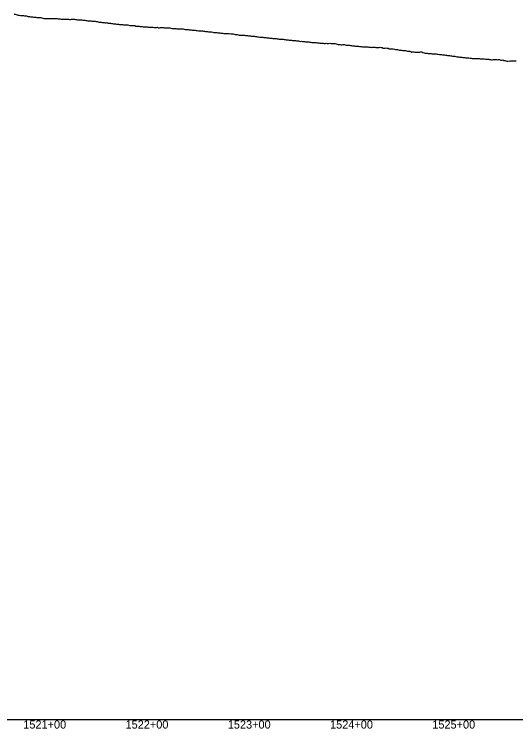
# Model space of a CAD drawing. Extents: x -3793 to 50787, y -1075 to 6138.
# Drawn here: x 39450 to 39940, y 991 to 1689 of the extents above; entities that cross this region are included whole.
import ezdxf

# ---------------------------------------------------------------- set-up
doc = ezdxf.new("R2010")
doc.units = 0
for name, color, linetype in [('RD_DDB_Profile_EX', 7, 'Continuous'), ('RD_DDB_StaTX', 7, 'Continuous'), ('RD_GPK_Profile_Cell', 7, 'Continuous')]:
    doc.layers.add(name, color=color, linetype=linetype)

msp = doc.modelspace()

# ---------------------------------------------------------------- linework, layer by layer
at = {"layer": 'RD_DDB_Profile_EX'}
for points in [[(39449.537684, 1689.40736), (39450.542169, 1689.40942), (39451.544989, 1689.208105), (39452.53964, 1688.9621), (39453.542457, 1688.56125), (39454.545276, 1688.459445), (39455.539896, 1688.36386), (39456.542717, 1688.311505), (39457.54554, 1688.259075), (39458.538528, 1688.15812), (39459.541346, 1688.00625), (39460.54417, 1687.85403), (39461.537143, 1687.752555), (39462.791116, 1687.374955), (39463.543266, 1687.301515), (39464.536597, 1687.102635), (39465.540058, 1687.00463), (39466.54352, 1686.956515), (39467.536879, 1686.807795), (39468.540329, 1686.71492), (39469.543797, 1686.51695), (39470.547266, 1686.46765), (39471.540601, 1686.367695), (39472.544069, 1686.317545), (39473.547537, 1686.120875), (39474.540963, 1686.21834), (39475.544439, 1686.170315), (39476.547915, 1685.825485), (39477.541364, 1685.629255), (39478.54473, 1685.185275), (39479.548205, 1685.13814), (39480.541674, 1685.190135), (39481.545157, 1685.33708), (39482.54864, 1685.43415), (39483.552123, 1685.334445), (39484.545467, 1685.236235)], [(39484.545467, 1685.236235), (39485.54895, 1685.238005), (39486.552434, 1685.288085), (39487.545954, 1685.392585), (39488.549445, 1685.39808), (39489.552936, 1685.3001), (39490.546481, 1685.201325), (39491.549776, 1685.151335), (39492.553267, 1685.054345), (39493.546833, 1684.905565), (39494.550332, 1684.80869), (39495.553831, 1684.71305), (39496.557331, 1684.66639), (39497.55093, 1684.760475), (39498.554184, 1684.663675), (39499.55774, 1684.6218), (39500.551379, 1684.668855), (39501.554887, 1684.620815), (39502.558395, 1684.527235), (39503.552061, 1684.460405), (39504.555263, 1684.41665), (39505.558772, 1684.50885), (39506.552459, 1684.556555), (39507.555976, 1684.703015), (39508.559493, 1684.60772), (39509.56301, 1684.31955), (39510.556734, 1684.22411), (39511.559893, 1684.034855), (39512.563411, 1683.983115), (39513.557157, 1684.03242), (39514.560683, 1683.98618), (39515.56421, 1683.888075), (39516.557984, 1683.78927), (39517.561108, 1683.683045), (39518.564635, 1683.63479), (39519.558433, 1683.20266), (39520.561957, 1683.250085), (39521.565042, 1683.151665), (39522.568564, 1683.05127), (39523.561925, 1682.949865), (39524.565447, 1682.899335), (39525.568964, 1682.80312), (39526.562325, 1682.753905), (39527.565847, 1682.705625), (39528.56888, 1682.602345), (39529.562724, 1682.460315), (39530.566359, 1682.26633), (39531.569354, 1682.11781), (39532.572863, 1681.784885), (39533.566225, 1681.778175), (39534.569734, 1681.632425), (39535.573247, 1681.29506), (39536.566604, 1681.33784), (39537.570112, 1681.289495), (39538.573063, 1681.19137), (39539.566982, 1681.183875), (39540.569917, 1681.226915), (39541.573423, 1680.69289), (39542.567359, 1680.69374), (39543.570277, 1680.739475), (39544.573783, 1680.43832), (39545.576681, 1680.34571), (39546.570641, 1680.2028), (39547.574142, 1680.104405), (39548.577023, 1680.143725), (39549.571, 1679.750935), (39550.57387, 1679.702415), (39551.577364, 1679.69137), (39552.570717, 1679.54549), (39553.574211, 1679.496915), (39554.577705, 1679.572535), (39555.580577, 1679.337285), (39556.574605, 1679.058125), (39557.577411, 1678.96289), (39558.580937, 1679.008285), (39559.584424, 1679.05963), (39560.577807, 1679.049855), (39561.581295, 1678.61949), (39562.584029, 1678.478215), (39563.58753, 1678.4649), (39564.581653, 1678.45784), (39565.584353, 1678.462855), (39566.587854, 1678.467945), (39567.590519, 1678.36909), (39568.584677, 1677.90202), (39569.587334, 1677.866285), (39570.590809, 1677.850995), (39571.594285, 1677.798485), (39572.587624, 1677.52893), (39573.5911, 1677.343435), (39574.593687, 1677.34097), (39575.597141, 1677.251525), (39576.591391, 1677.238765), (39577.593929, 1677.194925), (39578.5974, 1677.146345), (39579.599923, 1677.13367), (39580.594189, 1676.95793), (39581.596686, 1676.949675), (39582.600147, 1676.716005), (39583.603579, 1676.67189), (39584.596914, 1676.762595)], [(39584.596914, 1676.762595), (39585.600376, 1676.71444), (39586.602776, 1676.490345), (39587.606237, 1676.45204), (39588.600605, 1676.6519), (39589.602976, 1676.791225), (39590.606436, 1676.16088), (39591.608817, 1676.29161), (39592.603176, 1676.380415), (39593.606637, 1676.538365), (39594.608924, 1676.53218), (39595.61238, 1676.39431), (39596.605704, 1676.30632), (39597.609097, 1676.266675), (39598.611399, 1676.29621), (39599.614841, 1676.147975), (39600.60927, 1676.09091), (39601.611534, 1676.024965), (39602.614975, 1675.738325), (39603.618339, 1675.5617), (39604.611659, 1675.600685), (39605.615111, 1675.64581), (39606.618476, 1675.551175), (39607.620666, 1675.42127), (39608.615237, 1675.17857), (39609.618602, 1675.14696), (39610.62076, 1675.15505), (39611.624208, 1675.11814), (39612.61874, 1675.066475), (39613.620868, 1675.055045), (39614.624213, 1675.227125), (39615.627648, 1674.97495), (39616.620978, 1674.65853), (39617.624323, 1674.614325), (39618.627758, 1674.51612), (39619.629814, 1674.39738), (39620.62442, 1674.3453), (39621.627869, 1674.289445), (39622.629896, 1674.10489), (39623.633221, 1674.01737), (39624.627967, 1674.011375), (39625.629962, 1673.94161), (39626.633305, 1673.7461), (39627.636734, 1673.519415), (39628.630046, 1673.42038), (39629.633373, 1673.37574), (39630.636802, 1673.32742), (39631.638631, 1673.23201), (39632.633459, 1673.168055), (39633.636888, 1673.11212), (39634.638669, 1673.05937), (39635.642092, 1672.776265), (39636.636976, 1672.68435), (39637.638729, 1672.547205), (39638.642152, 1672.44105), (39639.645575, 1672.39268), (39640.638769, 1672.228915), (39641.642192, 1672.180675), (39642.645637, 1672.149735), (39643.647309, 1672.054745), (39644.642255, 1671.63695), (39645.645791, 1671.560475), (39646.639214, 1671.465575), (39647.642772, 1671.454645), (39648.637699, 1671.389845), (39649.639618, 1671.27969), (39650.643155, 1671.17765), (39651.63817, 1671.08284), (39652.640022, 1671.002245), (39653.635031, 1670.865385), (39654.638561, 1670.782165), (39655.631975, 1670.6451), (39656.635404, 1670.654555), (39657.630397, 1670.685835), (39658.632366, 1670.54148), (39659.635896, 1670.44715), (39660.630758, 1670.509955), (39661.632739, 1670.288505), (39662.627701, 1670.242815), (39663.631224, 1670.14079), (39664.62454, 1669.891785), (39665.628063, 1669.78975), (39666.622974, 1669.644535), (39667.625006, 1669.57689), (39668.62853, 1669.33223), (39669.623338, 1669.11282), (39670.625369, 1669.06049), (39671.620247, 1669.135755), (39672.623776, 1669.04021), (39673.617096, 1668.984005), (39674.620612, 1668.938655), (39675.624128, 1668.79394), (39676.617523, 1668.69133), (39677.620964, 1668.585795), (39678.615805, 1668.48275), (39679.617888, 1668.43076), (39680.612707, 1668.291655), (39681.614749, 1667.97058), (39682.609568, 1668.025025), (39683.611697, 1667.97933), (39684.613862, 1667.86257)], [(39684.613862, 1667.86257), (39685.608569, 1667.763005), (39686.610745, 1667.58694), (39687.605516, 1667.477045), (39688.607705, 1667.33102), (39689.602388, 1667.14418), (39690.604587, 1667.04138), (39691.59802, 1666.93088), (39692.601559, 1666.878235), (39693.603821, 1666.812205), (39694.59844, 1666.67546), (39695.600713, 1666.5785), (39696.595411, 1666.462675), (39697.59771, 1666.328055), (39698.591037, 1666.2847), (39699.594586, 1666.17578), (39700.588032, 1666.083915), (39701.591581, 1665.93711), (39702.593818, 1665.869625), (39703.58847, 1665.816265), (39704.590838, 1665.71885), (39705.584283, 1665.61534), (39706.587737, 1665.50434), (39707.581182, 1665.350975), (39708.584755, 1665.242105), (39709.587165, 1665.14511), (39710.581638, 1665.078615), (39711.584073, 1665.064345), (39712.57753, 1664.96688), (39713.581115, 1664.75301), (39714.574437, 1664.669975), (39715.578021, 1664.572515), (39716.571477, 1664.41931), (39717.575061, 1664.32168), (39718.577561, 1664.24794), (39719.570899, 1664.11382), (39720.574476, 1664.026995), (39721.567944, 1663.92362), (39722.571539, 1663.830725), (39723.564858, 1663.77105), (39724.568451, 1663.628075), (39725.561919, 1663.489565), (39726.564515, 1663.381195), (39727.567938, 1663.29246), (39728.561436, 1663.188265), (39729.565022, 1662.954685), (39730.558519, 1662.995455), (39731.560974, 1662.94686), (39732.555421, 1662.838315), (39733.558081, 1662.694095), (39734.552504, 1662.581005), (39735.555008, 1662.481945), (39736.558603, 1662.428945), (39737.552112, 1662.374685), (39738.554808, 1662.27607), (39739.549038, 1662.121915), (39740.551742, 1661.973265), (39741.54614, 1661.923385), (39742.548868, 1661.874525), (39743.543226, 1661.783305), (39744.545801, 1661.66837), (39745.548557, 1661.52722), (39746.542925, 1661.45545), (39747.545704, 1661.401775), (39748.539855, 1661.28996), (39749.542643, 1661.22434), (39750.536977, 1661.131695), (39751.539788, 1661.016435), (39752.542417, 1660.909745), (39753.536725, 1660.855765), (39754.539565, 1661.133385), (39755.458192, 1660.991235), (39756.321414, 1660.797695), (39757.314519, 1660.794705), (39758.319066, 1661.10038), (39759.336518, 1660.862645), (39760.317491, 1660.724665), (39761.321776, 1660.75733), (39762.324038, 1660.851215), (39763.317888, 1660.8019), (39764.322283, 1660.567775), (39765.324435, 1660.103005), (39766.318284, 1659.86507), (39767.321949, 1659.8153), (39768.315791, 1659.71252), (39769.31868, 1659.61468), (39770.322345, 1659.63548), (39771.316186, 1659.775215), (39772.31834, 1659.81957), (39773.32274, 1659.477785), (39774.315851, 1659.378515), (39775.32025, 1659.32921), (39776.323136, 1659.19213), (39777.316247, 1659.096585), (39778.320644, 1658.98251), (39779.322918, 1658.962085), (39780.316642, 1658.54255), (39781.32032, 1658.489365), (39782.314148, 1658.493845), (39783.317036, 1658.392195), (39784.320715, 1658.28902)], [(39784.320715, 1658.28902), (39785.314542, 1658.20076), (39786.316817, 1658.09141), (39787.321109, 1658.03867), (39788.314935, 1657.946765), (39789.317212, 1657.81776), (39790.321502, 1657.749715), (39791.314611, 1657.67895), (39792.319011, 1657.507455), (39793.321293, 1657.50915), (39794.315004, 1657.653225), (39795.319403, 1657.42852), (39796.321686, 1657.387215), (39797.315507, 1657.309685), (39798.31909, 1657.181695), (39799.312903, 1657.08252), (39800.315187, 1657.180445), (39801.31959, 1657.2739), (39802.312697, 1657.21394), (39803.315798, 1656.96149), (39804.319498, 1657.005155), (39805.313411, 1656.780385), (39806.315809, 1656.856485), (39807.320211, 1657.1969), (39808.313424, 1656.86487), (39809.315715, 1656.841465), (39810.311034, 1656.279865), (39811.314752, 1656.138985), (39812.317843, 1656.196935), (39813.312465, 1656.62637), (39814.316867, 1656.42734), (39815.310069, 1656.147815), (39816.313814, 1655.76492), (39817.318322, 1655.661645), (39818.311419, 1655.612415), (39819.315922, 1655.539845), (39820.310538, 1655.486165), (39821.313517, 1655.406675), (39822.308128, 1654.90264), (39823.31192, 1654.896585), (39824.314989, 1654.89166), (39825.309511, 1654.55632), (39826.314008, 1654.28804), (39827.307188, 1654.1975), (39828.31159, 1654.259285), (39829.315507, 1654.00575), (39830.308592, 1653.959525), (39831.313087, 1653.95887), (39832.30761, 1653.84632), (39833.310663, 1653.747735), (39834.314602, 1653.449845), (39835.309669, 1653.44583), (39836.312177, 1653.272595), (39837.306703, 1652.90125), (39838.311192, 1652.51873), (39839.304269, 1652.54593), (39840.308755, 1652.584585), (39841.312732, 1652.533705), (39842.306313, 1652.416695), (39843.310294, 1652.416085), (39844.30482, 1652.427165), (39845.307851, 1652.42619), (39846.311775, 1652.510855), (39847.306853, 1652.595105), (39848.309406, 1652.68196), (39849.304398, 1652.050045), (39850.308417, 1651.7608), (39851.301483, 1651.446335), (39852.305961, 1651.47653), (39853.309929, 1651.40979), (39854.303501, 1651.21498), (39855.30754, 1651.163695), (39856.302491, 1651.063875), (39857.305079, 1650.96979), (39858.309423, 1650.868735), (39859.304232, 1650.810735), (39860.306637, 1650.810995), (39861.301448, 1650.613365), (39862.305672, 1650.640505), (39863.299005, 1650.547945), (39864.303289, 1650.28921), (39865.307578, 1650.144335), (39866.300902, 1650.047745), (39867.304806, 1649.987105), (39868.299538, 1649.833735), (39869.302357, 1649.735945), (39870.306653, 1649.68506), (39871.301434, 1649.57775), (39872.304257, 1649.48365), (39873.298975, 1649.217505), (39874.302922, 1649.16843), (39875.296214, 1649.066175), (39876.300516, 1648.91882), (39877.33908, 1648.863075), (39878.298052, 1648.62279), (39879.302356, 1648.47329), (39880.297108, 1648.38253), (39881.301415, 1648.07123), (39882.305421, 1647.964955), (39883.298675, 1647.85855), (39884.302946, 1647.75738)], [(39884.302946, 1647.75738), (39885.297682, 1647.60655), (39886.302003, 1647.45783), (39887.296722, 1647.355105), (39888.29956, 1647.30896), (39889.293959, 1647.25758), (39890.29829, 1647.146265), (39891.302626, 1646.99438), (39892.297329, 1646.84022), (39893.325257, 1646.78258), (39894.294825, 1646.73498), (39895.299162, 1646.584145), (39896.293839, 1646.383245), (39897.297972, 1646.32771), (39898.292642, 1646.224405), (39899.315995, 1646.221265), (39900.29981, 1646.3216), (39901.29447, 1646.31085), (39902.298826, 1646.209555), (39903.293467, 1646.15468), (39904.297674, 1646.048455), (39905.292286, 1645.89543), (39906.29514, 1645.84977), (39907.299511, 1645.745195), (39908.294135, 1645.789945), (39909.29851, 1645.88515), (39910.303628, 1645.384705), (39911.295959, 1645.485705), (39912.290472, 1645.48015), (39913.294883, 1645.3775), (39914.289413, 1645.322365), (39915.293825, 1645.220025), (39916.298181, 1644.91776), (39917.29124, 1644.82011), (39918.295602, 1645.363475), (39919.290184, 1645.35938), (39920.294567, 1645.206875), (39921.289118, 1645.1036), (39922.293523, 1644.950835), (39923.286524, 1645.051705), (39923.952353, 1645.11629), (39924.291039, 1645.1512), (39925.295752, 1644.505415), (39926.290695, 1644.560435), (39927.29538, 1644.81281), (39928.290343, 1644.319965), (39929.293028, 1644.218425), (39930.287947, 1643.87554), (39931.292672, 1643.72889), (39932.297324, 1643.732965), (39933.292307, 1643.738475), (39934.295001, 1643.733725), (39935.289929, 1643.88713), (39936.294633, 1643.83947), (39937.289558, 1643.843715), (39938.294281, 1643.84808), (39939.289312, 1643.952795), (39940.293898, 1643.75439)]]:
    msp.add_lwpolyline(points, dxfattribs=at)
at = {"layer": 'RD_GPK_Profile_Cell'}
msp.add_line((1000, 1000), (46600, 1000), dxfattribs=at)

# ---------------------------------------------------------------- texts
at = {"layer": 'RD_DDB_StaTX'}
for s, p in [('1521+00', (39458.415471, 991)), ('1522+00', (39558.415471, 991)), ('1523+00', (39658.415471, 991)), ('1524+00', (39758.415471, 991)), ('1525+00', (39858.415471, 991))]:
    msp.add_text(s, height=8, dxfattribs=at).set_placement(p)

doc.saveas('drawing.dxf')
